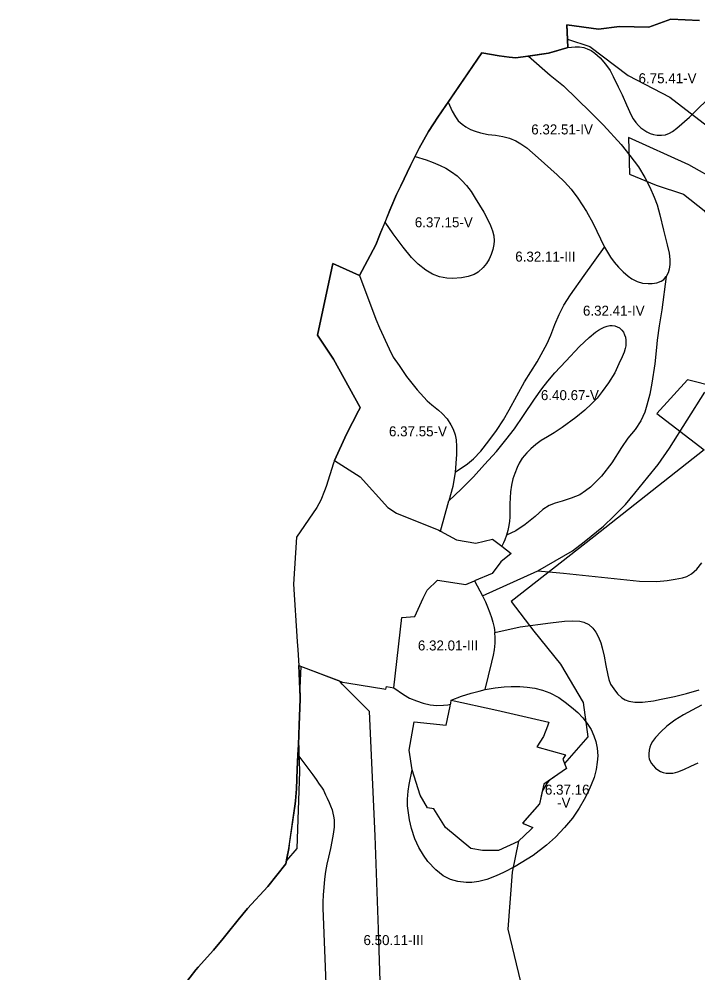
# Model space of a CAD drawing. Extents: x -555156 to -540209, y -1046851 to -1035695.
# Drawn here: x -544847 to -544168, y -1041591 to -1040636 of the extents above; entities that cross this region are included whole.
import ezdxf

# ---------------------------------------------------------------- set-up
doc = ezdxf.new("R2010")
doc.units = 0
for name, color, linetype in [('Vrstva 27', 7, 'Continuous'), ('Vrstva 28', 7, 'Continuous'), ('Vrstva 29', 7, 'Continuous')]:
    doc.layers.add(name, color=color, linetype=linetype)

msp = doc.modelspace()

# ---------------------------------------------------------------- linework, layer by layer
at = {"layer": 'Vrstva 28'}
for points in [[(-544166.22, -1040637.59), (-544194.81, -1040636.28), (-544216.62, -1040644.41), (-544246.26, -1040643.8), (-544267.15, -1040646.48), (-544298.67, -1040642.1), (-544297.7, -1040664.73), (-544298.9, -1040665.07), (-544317.06, -1040670.29), (-544337.8, -1040673.39), (-544349.95, -1040675.2), (-544356.55, -1040674.31), (-544366.62, -1040672.96), (-544383.79, -1040670.03), (-544427.71, -1040734.58), (-544432.1, -1040741.26), (-544437.02, -1040748.73), (-544446.44, -1040765.48), (-544455.16, -1040782.8), (-544464.87, -1040803.18), (-544469.17, -1040811.99), (-544474.76, -1040825.21), (-544485.7, -1040851.88), (-544486.13, -1040852.93), (-544489.94, -1040862.21), (-544498.21, -1040877.82), (-544506.14, -1040892.78), (-544532.86, -1040880.86), (-544548.31, -1040952.59), (-544532.05, -1040976.51), (-544505.45, -1041025.02), (-544505.96, -1041026.02), (-544507.13, -1041028.3), (-544519.08, -1041051.59), (-544531.05, -1041078.03), (-544532.25, -1041080.68), (-544539.47, -1041104.24), (-544541.13, -1041108.34), (-544544.93, -1041117.72), (-544548.7, -1041125.15), (-544569.22, -1041154.9), (-544572.13, -1041201.92), (-544568.35, -1041259.22), (-544567.87, -1041267.57), (-544566.97, -1041283.29), (-544565.36, -1041316.96), (-544566.42, -1041342.62), (-544567.24, -1041362.64), (-544568.61, -1041387.02), (-544569.32, -1041406.66), (-544570.32, -1041418.62), (-544570.58, -1041421.76), (-544576.37, -1041462.2), (-544576.99, -1041466.5), (-544579.99, -1041481.73), (-544597.99, -1041504.33), (-544618.31, -1041526.55), (-544627.44, -1041537.8), (-544635.8, -1041548.1), (-544641.15, -1041554.7), (-544642.56, -1041556.41), (-544652.1, -1041568.04), (-544667.51, -1041585.3), (-544669.81, -1041587.89), (-544692.4, -1041617.08)], [(-544297.7, -1040664.73), (-544298.67, -1040642.1), (-544267.15, -1040646.48), (-544246.26, -1040643.8), (-544216.62, -1040644.41), (-544194.81, -1040636.28), (-544166.22, -1040637.59)], [(-544337.12, -1040673.29), (-544317.06, -1040670.29), (-544313.49, -1040669.26), (-544298.9, -1040665.07), (-544297.7, -1040664.73)], [(-544297.7, -1040664.73), (-544290.43, -1040664.05), (-544285.95, -1040664.05), (-544281.83, -1040664.78)], [(-544281.83, -1040664.78), (-544278.32, -1040665.99), (-544274.45, -1040667.81), (-544270.69, -1040670.47), (-544265.48, -1040674.96), (-544260.03, -1040681.26), (-544255.55, -1040687.8), (-544252.28, -1040693.86), (-544247.56, -1040704.04), (-544243.44, -1040712.03), (-544238.96, -1040722.21), (-544234.48, -1040732.39), (-544232.4, -1040736.18), (-544229.84, -1040739.85), (-544227.21, -1040742.76), (-544224.72, -1040745.11), (-544221.75, -1040747.19), (-544218.63, -1040749.27), (-544215.45, -1040750.65), (-544211.99, -1040751.83), (-544208.32, -1040752.59), (-544204.17, -1040752.59), (-544199.95, -1040751.97), (-544196.14, -1040750.58), (-544193.17, -1040748.85), (-544188.6, -1040745.32), (-544176.07, -1040734.52), (-544150.81, -1040709.32)], [(-544417.51, -1040719.59), (-544383.79, -1040670.03), (-544366.62, -1040672.96)], [(-544366.62, -1040672.96), (-544356.55, -1040674.31), (-544349.95, -1040675.2), (-544337.8, -1040673.39), (-544337.12, -1040673.29)], [(-544337.12, -1040673.29), (-544315.38, -1040692.42), (-544302.18, -1040703.08), (-544288.73, -1040716.05), (-544274.93, -1040729.62), (-544261.97, -1040742.34), (-544244.38, -1040761.75), (-544235.78, -1040772.9), (-544227.18, -1040784.05), (-544220.88, -1040794.71), (-544215.68, -1040804.53), (-544211.56, -1040814.46), (-544208.41, -1040822.34), (-544205.62, -1040832.15), (-544202.13, -1040847.38), (-544198.33, -1040862.13), (-544196.46, -1040870.65), (-544195.63, -1040876.88), (-544195.7, -1040881.93), (-544196.25, -1040886.57), (-544197.41, -1040890.11), (-544199.35, -1040893.98)], [(-544450.57, -1040773.69), (-544446.44, -1040765.48), (-544437.02, -1040748.73), (-544432.1, -1040741.26), (-544427.71, -1040734.58), (-544417.51, -1040719.59)], [(-544417.51, -1040719.59), (-544413.32, -1040728.52)], [(-544413.32, -1040728.52), (-544410.3, -1040734.09), (-544407.39, -1040737.97), (-544403.51, -1040741.48), (-544399.64, -1040744.27), (-544395.28, -1040746.69), (-544390.31, -1040748.51), (-544384.99, -1040749.97), (-544377.36, -1040751.66), (-544369.97, -1040752.63), (-544362.94, -1040753.84), (-544356.28, -1040755.54), (-544349.74, -1040758.21), (-544344.66, -1040761.24), (-544338.72, -1040765.23), (-544327.58, -1040775.17), (-544308.32, -1040792.26), (-544300.97, -1040799.23), (-544294.56, -1040806.5), (-544287.77, -1040815.35), (-544279.05, -1040828.92), (-544272.64, -1040840.31), (-544261.01, -1040864.42)], [(-544480.63, -1040839.53), (-544475, -1040825.8), (-544474.76, -1040825.21), (-544469.17, -1040811.99), (-544465.86, -1040805.21), (-544464.87, -1040803.18), (-544455.16, -1040782.8), (-544450.57, -1040773.69)], [(-544439.63, -1040777.25), (-544432.36, -1040779.8), (-544425.58, -1040782.83), (-544419.77, -1040785.62), (-544414.2, -1040789.01), (-544408.63, -1040793.25), (-544403.66, -1040797.73), (-544399.06, -1040802.82), (-544394.58, -1040808.88), (-544390.34, -1040815.54), (-544385.98, -1040822.57), (-544381.74, -1040829.6), (-544378.13, -1040836.46), (-544375.1, -1040842.76), (-544373.04, -1040848.09), (-544371.83, -1040853.31), (-544371.47, -1040858.15), (-544371.71, -1040862.03), (-544372.8, -1040866.88), (-544374.62, -1040871.97), (-544376.56, -1040876.45), (-544379.22, -1040880.81), (-544382.37, -1040885.05), (-544387.58, -1040889.54), (-544391.45, -1040891.84), (-544397.39, -1040894.02), (-544404.29, -1040895.35), (-544413.01, -1040895.96), (-544418.74, -1040895.61), (-544426.25, -1040894.28), (-544433.15, -1040891.61), (-544439.93, -1040887.74), (-544447.44, -1040881.56), (-544454.1, -1040874.89), (-544462.58, -1040864.59), (-544472.6, -1040851.17), (-544480.63, -1040839.53)], [(-544450.57, -1040773.69), (-544439.63, -1040777.25)], [(-544506.14, -1040892.78), (-544498.21, -1040877.82), (-544489.94, -1040862.21), (-544486.13, -1040852.93), (-544485.7, -1040851.88), (-544480.63, -1040839.53)], [(-544410.51, -1041089.73), (-544398.22, -1041081.29), (-544392.28, -1041076.56), (-544384.74, -1041068.68), (-544376.69, -1041058.51), (-544369.27, -1041047.9), (-544362.28, -1041037.51), (-544356.55, -1041027.33), (-544341.14, -1040999.49), (-544328.42, -1040979.34), (-544318.46, -1040961.11), (-544314.64, -1040952.63), (-544310.83, -1040942.02), (-544306.59, -1040932.06), (-544301.72, -1040922.51), (-544295.15, -1040912.12), (-544281.37, -1040893.04), (-544261.01, -1040864.42)], [(-544261.01, -1040864.42), (-544258.17, -1040869.54)], [(-544258.17, -1040869.54), (-544255.06, -1040874.53), (-544251.39, -1040879.51), (-544247.1, -1040884.5), (-544242.39, -1040889.21), (-544237.48, -1040893.71), (-544233.81, -1040896.41), (-544228.55, -1040898.9), (-544222.95, -1040900.49), (-544217.55, -1040901.05), (-544213.4, -1040900.98), (-544208.69, -1040900.21), (-544204.47, -1040898.55), (-544201.77, -1040896.82), (-544199.35, -1040893.98)], [(-544531.05, -1041078.03), (-544519.08, -1041051.59), (-544507.13, -1041028.3), (-544505.96, -1041026.02), (-544505.45, -1041025.02), (-544532.05, -1040976.51), (-544548.31, -1040952.59), (-544532.86, -1040880.86), (-544506.14, -1040892.78)], [(-544506.14, -1040892.78), (-544489.84, -1040936.53), (-544486.21, -1040945.38), (-544476.4, -1040966.22), (-544472.37, -1040974.58), (-544466.43, -1040983.07), (-544459.23, -1040993.88), (-544448.42, -1041007.45), (-544438.46, -1041018.48), (-544433.76, -1041022.48), (-544427.22, -1041027.57), (-544423.47, -1041031.08), (-544418.5, -1041036.41), (-544414.75, -1041042.23), (-544412.33, -1041046.83), (-544410.51, -1041052.28), (-544409.54, -1041057.25), (-544409.06, -1041063.92), (-544409.18, -1041072.16), (-544410.51, -1041089.73)], [(-544199.35, -1040893.98), (-544203.78, -1040927.24), (-544206.32, -1040943.36), (-544208.26, -1040957.78), (-544208.99, -1040965.1), (-544210.9, -1040981.43), (-544213.66, -1041000.73), (-544215.78, -1041011.75), (-544218.74, -1041022.78), (-544220.65, -1041029.78), (-544224.68, -1041038.47), (-544230.4, -1041047.17), (-544237.61, -1041055.86), (-544244.18, -1041065.19), (-544253.71, -1041080.46), (-544264.1, -1041093.82), (-544275.14, -1041104.69), (-544280.22, -1041108.45), (-544285.91, -1041112.33), (-544294.51, -1041115.84), (-544303.47, -1041118.75), (-544310.38, -1041120.81), (-544316.55, -1041123.23), (-544322.85, -1041126.99), (-544330.48, -1041134.02), (-544340.29, -1041142.14), (-544349.62, -1041148.32), (-544359.15, -1041152.94)], [(-544416.91, -1041118.46), (-544404.51, -1041106.85), (-544392.04, -1041094.49), (-544381.02, -1041082.14), (-544369.03, -1041069.17), (-544359.7, -1041057.54), (-544351.23, -1041046.27), (-544342.14, -1041033.06), (-544331, -1041016.7), (-544323.85, -1041006.36), (-544317.79, -1040998.73), (-544310.65, -1040990.49), (-544299.75, -1040978.49), (-544285.94, -1040963.95), (-544276.37, -1040954.99), (-544270.08, -1040949.53), (-544267.15, -1040947.46), (-544264.11, -1040945.8), (-544261.27, -1040944.48), (-544258.43, -1040943.58), (-544255.8, -1040943.1), (-544253.45, -1040943.03), (-544250.82, -1040943.37)], [(-544250.82, -1040943.37), (-544248.33, -1040944.13), (-544246.18, -1040945.38), (-544243.69, -1040947.53), (-544242.17, -1040949.53), (-544240.99, -1040952.17), (-544240.23, -1040954.59), (-544239.68, -1040957.5), (-544239.61, -1040960.27), (-544239.75, -1040963.18), (-544240.3, -1040966.01), (-544241.48, -1040969.55), (-544243.42, -1040974.39), (-544246.67, -1040981.39), (-544250.89, -1040990.18), (-544257, -1041000.2), (-544263.54, -1041009.17), (-544268.5, -1041015.71), (-544273.95, -1041021.41), (-544280.73, -1041027.83), (-544289.7, -1041035.1), (-544303.36, -1041044.89), (-544311.35, -1041050.22), (-544318.25, -1041054.22), (-544324.31, -1041057.98), (-544329.64, -1041061.98), (-544334.85, -1041066.46), (-544338.84, -1041070.34), (-544343.45, -1041075.79), (-544346.47, -1041080.64), (-544348.41, -1041085), (-544350.95, -1041091.06), (-544352.77, -1041096.51), (-544354.1, -1041102.69), (-544355.19, -1041109.36), (-544355.4, -1041115.5), (-544355.76, -1041121.56), (-544355.76, -1041129.55), (-544355.88, -1041134.76), (-544356.12, -1041138.76), (-544356.73, -1041143.12), (-544357.7, -1041147.97), (-544359.15, -1041152.94)], [(-544327.75, -1041188.42), (-544292.99, -1041168.49), (-544281.33, -1041159.58), (-544262.05, -1041143.68), (-544251.66, -1041133.93), (-544240.01, -1041122.05), (-544230.68, -1041110.81), (-544217.75, -1041094.91), (-544207.58, -1041082.19), (-544196.12, -1041065.58), (-544160.88, -1041009.55)], [(-544531.05, -1041078.03), (-544505.5, -1041094.54)], [(-544505.5, -1041094.54), (-544477.93, -1041125.21), (-544469.11, -1041130.94), (-544426.84, -1041147.85), (-544425.02, -1041148.85)], [(-544410.51, -1041089.73), (-544412.91, -1041103.92), (-544416.91, -1041118.46)], [(-544425.02, -1041148.85), (-544416.91, -1041118.46)], [(-544425.02, -1041148.85), (-544409.25, -1041157.5), (-544389.87, -1041160.96), (-544372.99, -1041156.68), (-544363.94, -1041163.74)], [(-544359.15, -1041152.94), (-544360.85, -1041157.54), (-544362.18, -1041160.57), (-544363.94, -1041163.74)], [(-544363.94, -1041163.74), (-544354.41, -1041171.17), (-544364.84, -1041179.58), (-544373.57, -1041191.13), (-544391.07, -1041198.47)], [(-544327.75, -1041188.42), (-544302.19, -1041190.84), (-544226.1, -1041198.69), (-544208.91, -1041199.11), (-544198.49, -1041198.02), (-544190.5, -1041196.93), (-544182.99, -1041195.36), (-544178.75, -1041194.02), (-544174.03, -1041191.36), (-544168.82, -1041186.75), (-544163.61, -1041180.57)], [(-544383.06, -1041213.66), (-544327.75, -1041188.42)], [(-544471.82, -1041305.55), (-544463.85, -1041235.22), (-544450.97, -1041234.05), (-544442.39, -1041215.95), (-544438.53, -1041207.8), (-544428.05, -1041197.92), (-544399.64, -1041202.06)], [(-544399.64, -1041202.06), (-544391.07, -1041198.47)], [(-544391.07, -1041198.47), (-544383.06, -1041213.66)], [(-544383.06, -1041213.66), (-544380.28, -1041219.67), (-544378.1, -1041224.64), (-544375.68, -1041230.45), (-544373.99, -1041235.3), (-544372.65, -1041239.91), (-544371.32, -1041245.36), (-544370.72, -1041250.08)], [(-544370.72, -1041250.08), (-544345.46, -1041244.67), (-544315.07, -1041240.56), (-544301.14, -1041238.74), (-544292.66, -1041238.5), (-544285.76, -1041238.86)], [(-544285.76, -1041238.86), (-544281.76, -1041239.83), (-544276.92, -1041242.25), (-544272.68, -1041245.89), (-544269.77, -1041250.01), (-544267.23, -1041254.85), (-544264.93, -1041260.43), (-544263.47, -1041265.52), (-544261.42, -1041273.76), (-544259.72, -1041283.09), (-544257.9, -1041292.78), (-544256.75, -1041297.29), (-544254.94, -1041302.02), (-544251.91, -1041306.75), (-544248.15, -1041311.47), (-544243.92, -1041315.47), (-544240.52, -1041317.53), (-544236.89, -1041318.86), (-544230.59, -1041319.95), (-544222.96, -1041320.07), (-544212.06, -1041318.5), (-544204.31, -1041316.8), (-544191.11, -1041314.26), (-544179.12, -1041311.23), (-544166.41, -1041307.71)], [(-544380.36, -1041307.3), (-544377.26, -1041293.46), (-544373.74, -1041279.89), (-544372.29, -1041272.98), (-544371.2, -1041267.65), (-544370.6, -1041260.87), (-544370.35, -1041255.54), (-544370.72, -1041250.08)], [(-544567.8, -1041372.55), (-544567.24, -1041362.64), (-544566.42, -1041342.62), (-544565.36, -1041316.96), (-544565.44, -1041315.3), (-544566.97, -1041283.29)], [(-544566.97, -1041283.29), (-544523.19, -1041299.91), (-544518.89, -1041300.6), (-544479.68, -1041306.9), (-544479, -1041304.18), (-544471.82, -1041305.55)], [(-544471.82, -1041305.55), (-544462.23, -1041312.27), (-544456.05, -1041315.78), (-544449.27, -1041318.69), (-544442.48, -1041320.87), (-544435.58, -1041322.57), (-544428.92, -1041323.17), (-544422.02, -1041323.05), (-544417.66, -1041322.44), (-544415.1, -1041321.81)], [(-544345.84, -1041304.27), (-544338.33, -1041304.87), (-544330.82, -1041305.96), (-544322.95, -1041308.02), (-544315.81, -1041310.45), (-544306.84, -1041315.3), (-544299.22, -1041320.87), (-544291.98, -1041326.47), (-544287.62, -1041330.22), (-544282.77, -1041335.55), (-544278.41, -1041341.25), (-544274.54, -1041347.43), (-544271.63, -1041353.49), (-544269.82, -1041359.3), (-544268.48, -1041366.09), (-544267.88, -1041373.48), (-544268.36, -1041379.9), (-544269.45, -1041387.17), (-544271.39, -1041395.17), (-544274.3, -1041402.68), (-544277.93, -1041410.44), (-544281.44, -1041417.34), (-544286.33, -1041426.02), (-544293.11, -1041435.96), (-544301.11, -1041445.41), (-544309.95, -1041455.11), (-544319.03, -1041462.98), (-544332.47, -1041473.28), (-544350.4, -1041484.31), (-544362.27, -1041490.37), (-544369.53, -1041493.64), (-544378.74, -1041497.27), (-544386.67, -1041499.3), (-544393.69, -1041500.39), (-544399.63, -1041500.27), (-544407.86, -1041499.42), (-544415.01, -1041497.36), (-544422.52, -1041493.85), (-544429.9, -1041487.67), (-544437.66, -1041479.43), (-544442.14, -1041473.01), (-544446.74, -1041465.37), (-544450.86, -1041456.77), (-544454.13, -1041446.47), (-544456.18, -1041437.63), (-544457.22, -1041430.62), (-544458.07, -1041423.59), (-544458.07, -1041416.93), (-544457.59, -1041409.05), (-544456.5, -1041402.39), (-544453.6, -1041387.78)], [(-544380.36, -1041307.3), (-544370.3, -1041305.48), (-544361.34, -1041304.51), (-544354.44, -1041304.15), (-544345.84, -1041304.27)], [(-544414.33, -1041317.95), (-544403.97, -1041313.96), (-544394.41, -1041310.81), (-544386.41, -1041308.99), (-544380.36, -1041307.3)], [(-544453.6, -1041387.78), (-544456.34, -1041367.99), (-544451.58, -1041339.62), (-544419.35, -1041343.11), (-544415.5, -1041323.8), (-544415.1, -1041321.81)], [(-544415.1, -1041321.81), (-544414.97, -1041321.14), (-544414.33, -1041317.95)], [(-544414.33, -1041317.95), (-544368.63, -1041327.79)], [(-544164.16, -1041323.01), (-544173.48, -1041328.1), (-544182.09, -1041332.54), (-544190.6, -1041337.87), (-544198.7, -1041343.89), (-544204.86, -1041349.57), (-544210.05, -1041355.39), (-544213.16, -1041359.33), (-544214.75, -1041362.31), (-544215.77, -1041365.01), (-544216.46, -1041367.99), (-544216.81, -1041371.73), (-544216.67, -1041374.64), (-544216.33, -1041376.78), (-544215.56, -1041378.93), (-544214.11, -1041381.35), (-544212.52, -1041383.43), (-544209.96, -1041385.99), (-544207.68, -1041387.79), (-544205.05, -1041389.32), (-544202.28, -1041390.29), (-544199.51, -1041390.91), (-544195.7, -1041391.12), (-544192.73, -1041390.98), (-544189.96, -1041390.42), (-544187.61, -1041389.59), (-544181.72, -1041387.24), (-544174.87, -1041384.12), (-544167.46, -1041380.74)], [(-544368.63, -1041327.79), (-544316.91, -1041340.08), (-544318.24, -1041343.8), (-544321.97, -1041354.27), (-544328.62, -1041364.65), (-544300.23, -1041372.54), (-544302.87, -1041377.14), (-544299.16, -1041386.42), (-544321.85, -1041401.92), (-544326.26, -1041421.76), (-544343.12, -1041441.04), (-544332.76, -1041445.41), (-544334.52, -1041447.09), (-544347.45, -1041459.42), (-544367.28, -1041468.23), (-544383.19, -1041468.39), (-544394.79, -1041466.42), (-544420.09, -1041445.28), (-544431.8, -1041426.77), (-544438.03, -1041425.82), (-544445.52, -1041412.9), (-544453.6, -1041387.78)], [(-544846.66, -1041687.71), (-544822.15, -1041682.29), (-544785.01, -1041662.41), (-544782.28, -1041660.95), (-544732.45, -1041636.53), (-544706.67, -1041625.81), (-544692.4, -1041617.08), (-544669.81, -1041587.89), (-544667.51, -1041585.3), (-544652.1, -1041568.04), (-544642.56, -1041556.41), (-544641.15, -1041554.7), (-544627.44, -1041537.8), (-544618.31, -1041526.55), (-544597.99, -1041504.33), (-544579.99, -1041481.73), (-544578.85, -1041475.94), (-544576.99, -1041466.5), (-544570.58, -1041421.76), (-544570.32, -1041418.62), (-544569.32, -1041406.66), (-544568.61, -1041387.02), (-544567.8, -1041372.55)], [(-544567.8, -1041372.55), (-544552.69, -1041392.53)], [(-544552.69, -1041392.53), (-544549.36, -1041397.3), (-544546.39, -1041401.87), (-544544.1, -1041405.13), (-544542.31, -1041407.97), (-544540.02, -1041412.54), (-544538.36, -1041416.14), (-544536.42, -1041420.22), (-544535.04, -1041423.61), (-544533.65, -1041427.84), (-544532.69, -1041431.02), (-544532.13, -1041434.14), (-544531.65, -1041437.81), (-544531.58, -1041441.83), (-544531.65, -1041445.11), (-544532.38, -1041452.14), (-544533.83, -1041459.53), (-544535.05, -1041466.43), (-544537.23, -1041475.04), (-544538.68, -1041481.94), (-544540.01, -1041489.46), (-544541.22, -1041497.21), (-544541.95, -1041505.33), (-544542.55, -1041512.72), (-544542.92, -1041519.99), (-544542.8, -1041526.17), (-544542.44, -1041534.31), (-544539.68, -1041601.75)]]:
    msp.add_lwpolyline(points, dxfattribs=at)
at = {"layer": 'Vrstva 29'}
for points in [[(-544166.22, -1040637.59), (-544194.81, -1040636.28), (-544216.62, -1040644.41), (-544246.26, -1040643.8), (-544267.15, -1040646.48), (-544298.67, -1040642.1), (-544298.064531, -1040656.225529), (-544275.830994, -1040663.698975), (-544237.468018, -1040692.611023), (-544195.877991, -1040714.437988), (-544144.943909, -1040753.474976)], [(-544121.143005, -1040922.22699), (-544106.937012, -1040890.955017), (-544109.434021, -1040852.72998), (-544124.250977, -1040828.622986), (-544147.216003, -1040798.890991), (-544176.791016, -1040782.292908), (-544237.250977, -1040754.835999), (-544236.153015, -1040791.651978), (-544209.339905, -1040802.375977), (-544182.10498, -1040811.356995), (-544161.458984, -1040827.86499), (-544146.364014, -1040851.744019), (-544134.943909, -1040879.351013), (-544121.143005, -1040922.22699)], [(-544095.031982, -1041018.288025), (-544178.070984, -1040997.335999), (-544208.60199, -1041031.124023), (-544161.247009, -1041067.525024), (-544271.908997, -1041154.570984), (-544354.38501, -1041219.077026), (-544331.697021, -1041249.036987), (-544304.947998, -1041281.934998), (-544282.292908, -1041320.304993), (-544277.893982, -1041354.632019), (-544301.21391, -1041381.282457)], [(-544484.916992, -1041620.085999), (-544487.161011, -1041546.960022), (-544490.570984, -1041453.836975), (-544496.088013, -1041329.155029), (-544523.366028, -1041301.815002), (-544525.978736, -1041298.851325), (-544564.764163, -1041284.127392), (-544565.907064, -1041305.528286), (-544565.44, -1041315.3), (-544565.36, -1041316.96), (-544566.42, -1041342.62), (-544567.042081, -1041357.807868), (-544566.143005, -1041389.241028), (-544568.861023, -1041466.22699), (-544579.300063, -1041478.225848), (-544579.99, -1041481.73), (-544597.99, -1041504.33), (-544618.31, -1041526.55), (-544627.44, -1041537.8), (-544635.8, -1041548.1), (-544641.15, -1041554.7), (-544642.56, -1041556.41), (-544652.1, -1041568.04), (-544667.51, -1041585.3), (-544669.81, -1041587.89), (-544692.4, -1041617.08)], [(-544301.21391, -1041381.282457), (-544299.16, -1041386.42), (-544315.441973, -1041397.542547), (-544318.85498, -1041401.442993), (-544323.458198, -1041409.155069), (-544326.26, -1041421.76), (-544341.134812, -1041438.769868), (-544342.616569, -1041441.252354), (-544332.76, -1041445.41), (-544334.52, -1041447.09), (-544347.083654, -1041459.070654), (-544353.583008, -1041490.149902), (-544357.718018, -1041547.11499), (-544345.106995, -1041599.81897)]]:
    msp.add_lwpolyline(points, dxfattribs=at)

# ---------------------------------------------------------------- texts
at = {"layer": 'Vrstva 27'}
for s, p in [('6.75.41-V', (-544227.031006, -1040700.49)), ('6.32.51-IV', (-544334.367241, -1040751.73)), ('6.37.15-V', (-544450.836558, -1040844.65)), ('6.32.11-III', (-544350.376548, -1040878.99)), ('6.32.41-IV', (-544282.657241, -1040933.13)), ('6.40.67-V', (-544324.722993, -1041017.65)), ('6.37.55-V', (-544476.676558, -1041053.87)), ('6.32.01-III', (-544447.756548, -1041268.18)), ('6.37.16', (-544320.677329, -1041412.49)), ('-V', (-544308.464194, -1041425.49)), ('6.50.11-III', (-544502.186548, -1041563.06))]:
    msp.add_text(s, height=10, dxfattribs=at).set_placement(p)

doc.saveas('drawing.dxf')
